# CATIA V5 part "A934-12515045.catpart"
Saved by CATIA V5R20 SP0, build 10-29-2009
Part number: A934-12515045
Source: Unknown
Property "A": "85.000"
Property "ARTICLENO": "A934-12515045"
Property "B": "30.000"
Property "BOMINFO": "A934-12515045"
Property "CODE": "A934-12515045"
Property "L": "150.000"
Property "L1": "127.860"
Property "LINA": "A934-12515045"
Property "NB": "A934-12515045"
Property "NBSYN": "$CODE."
Property "NN": "A934"
Property "NT": "VDI 3357 H-Type Cam Drivers, self-lubricating"
Property "SUPPLIER": "CF"
Property "T": "45.000"
Property "W": "125.000"
Bounding box of the stored display mesh (mm): x 0 to 150, y 0 to 45, z -125 to 0
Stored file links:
  C:\Users\Utente\Desktop\3D files A934\A934-12515045.catpart
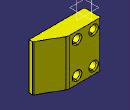
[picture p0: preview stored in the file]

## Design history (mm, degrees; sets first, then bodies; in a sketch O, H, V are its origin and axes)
Body1 "Geometry.1" (main body)
  Solid1 "A934-12515045.catpart": solid without history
